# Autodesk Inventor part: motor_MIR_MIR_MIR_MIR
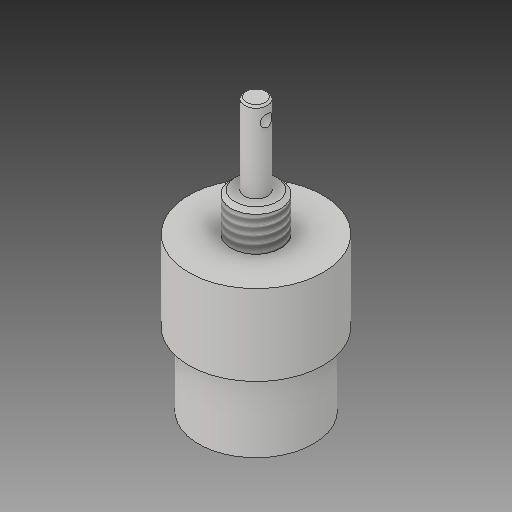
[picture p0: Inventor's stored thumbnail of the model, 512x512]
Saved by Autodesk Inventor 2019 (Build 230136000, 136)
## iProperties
Created: 2019-10
Part Number: motor_MIR_MIR_MIR_MIR
Material: Generic
Document SubType Name: Modeling
Designer: PRADYUMNA
Density: 1 g/cm^3
Appearance: Default
Author: Asus
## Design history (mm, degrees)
derived "motor_MIR_MIR_MIR.ipt"
  sketch "Sketch1"
    geometry: C1 r 6.5 at (0, 0) reference; 1 further point
  sketch "Sketch2"
    geometry: 1 further point
  sketch "Sketch3"
    geometry: C1 r 17.5 at (0, 0) reference; 1 further point
  sketch "Sketch4"
    geometry: C1 r 15 at (0, 0) reference; 1 further point
  sketch "Sketch5"
    geometry: C1 r 3 at (0, 0) reference; 1 further point
  sketch "Sketch6"
    geometry: C1 r 1.55 at (27.143, 0) reference; 1 further point
  sketch "Sketch7"
    geometry: L1 (12.192, 2.12)-(11.485, 2.12) reference; L2 (11.485, 2.12)-(11.485, -2.356) reference; L3 (11.485, -2.356)-(12.192, -2.356) reference; L4 (12.192, -2.356)-(12.192, 2.12) reference; L5 (-11.603, 2.12)-(-12.546, 2.12) reference; L6 (-12.546, 2.12)-(-12.546, -2.356) reference; L7 (-12.546, -2.356)-(-11.603, -2.356) reference; L8 (-11.603, -2.356)-(-11.603, 2.12) reference; 1 further point
feature "Solid1::motor_MIR_MIR_MIR.ipt"
tag "TaggingFeature1"
body "Solid1"
